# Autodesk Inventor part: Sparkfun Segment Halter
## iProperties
Created: 2016-11
Part Number: Sparkfun Segment Halter
Material: Standard
Document SubType Name: Blech
Designer: Acer
Density: 1 g/cm^3
Sheet Metal Rule: Standard_mm
Author: Acer
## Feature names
1. Extrusion1
2. Extrusion3
3. Extrusion4
4. Rundung1 [Fillet]
